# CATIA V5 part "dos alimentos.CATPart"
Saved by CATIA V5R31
Part number: dos alimentos
Bounding box of the stored display mesh (mm): x -77 to 71.25, y -71.051 to 71.051, z -5 to 175
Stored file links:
  C:\Users\189361\Desktop\piezas del comedero\piezas del comedero\dos alimentos.CATPart
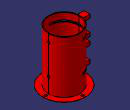
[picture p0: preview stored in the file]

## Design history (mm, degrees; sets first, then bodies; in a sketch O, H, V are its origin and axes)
Body1 (main body)
  Sketch1 on xy-plane, origin (0, 0, 0), H (1, 0, 0), V (0, 1, 0)
    construction circle A1 centre (0, 0) radius 62.25
    circle A2 centre (0, 62.25) radius 4.5
    point P1 (0, 62.25)
    circle A3 centre (62.25, 0) radius 4.5
    point P2 (62.25, 0)
    circle A4 centre (0, -62.25) radius 4.5
    circle A5 centre (-62.25, 0) radius 4.5
    circle A6 centre (0, 0) radius 71.25
    circle A7 centre (0, 0) radius 50
    circle A8 centre (0, 0) radius 52.5
    radius A1 = 62.25
    radius A2 = 4.5
    distance A3 A6 = 4.5
    radius A7 = 50
    radius A8 = 52.5
    coincidence: P1 A1, P1 V, P2 A1, P2 H
    equal size: A3 A2
    symmetry: A2 A4 H, A3 A5 V
  MultiPad1: profile Sketch1, domains (length 175 / length 5; length 0; length 0 / length 5; length 0; length 0; length 0; length 0)
  Fillet1: radius 5, on edge [face of MultiPad1 from Sketch1.A7 | face of MultiPad1]; edge [face of MultiPad1 | face of MultiPad1 from Sketch1.A6]
  Sketch2 on yz-plane, origin (0, 0, 0), H (0, 1, 0), V (0, 0, 1)
    construction line L1 (0, 0) -> (0, 50)
    construction line L2 (0, 0) -> (0, 150)
    point P2 (0, 150)
    arc A1 centre (0, 150) radius 4.25 from (4.25, 150) to (3.2404, 152.75) ccw
    point P3 (-50, 152.75)
    line L3 (-50, 152.75) -> (-3.2404, 152.75)
    line L4 (50, 152.75) -> (50, 147.25)
    line L5 (50, 147.25) -> (3.2404, 147.25)
    line L6 (-50, 147.25) -> (-50, 152.75)
    point P4 (50, 152.75)
    point P5 (50, 147.25)
    point P6 (-50, 147.25)
    axis line L7 (-80.1309, 100) -> (62.8872, 100)
    point P10 (-50, 47.25)
    point P11 (50, 47.25)
    point P12 (50, 52.75)
    point P13 (-50, 52.75)
    arc A2 centre (0, 50) radius 4.25 from (4.25, 50) to (3.2404, 47.25) cw
    line L8 (-50, 47.25) -> (-3.2404, 47.25)
    line L9 (50, 47.25) -> (50, 52.75)
    line L10 (50, 52.75) -> (3.2404, 52.75)
    line L11 (-50, 52.75) -> (-50, 47.25)
    point P14 (-3.2404, 147.25)
    line L12 (-3.2404, 147.25) -> (-50, 147.25)
    point P15 (3.2404, 147.25)
    point P16 (3.2404, 152.75)
    line L13 (3.2404, 152.75) -> (50, 152.75)
    point P17 (-3.2404, 152.75)
    point P18 (-3.2404, 52.75)
    line L14 (-3.2404, 52.75) -> (-50, 52.75)
    point P19 (3.2404, 52.75)
    point P20 (3.2404, 47.25)
    line L15 (3.2404, 47.25) -> (50, 47.25)
    point P21 (-3.2404, 47.25)
    point P22 (3.2404, 147.25)
    arc A3 centre (0, 150) radius 4.25 from (3.2404, 147.25) to (4.25, 150) ccw
    point P23 (4.25, 150)
    point P24 (4.25, 150)
    point P25 (3.2404, 152.75)
    arc A4 centre (0, 150) radius 4.25 from (3.2404, 152.75) to (-3.2404, 152.75) ccw
    point P26 (-3.2404, 152.75)
    arc A5 centre (0, 150) radius 4.25 from (-3.2404, 152.75) to (-3.2404, 147.25) ccw
    point P27 (-3.2404, 147.25)
    arc A6 centre (0, 150) radius 4.25 from (-3.2404, 147.25) to (3.2404, 147.25) ccw
    point P28 (-3.2404, 52.75)
    arc A7 centre (0, 50) radius 4.25 from (-3.2404, 52.75) to (3.2404, 52.75) cw
    point P29 (4.25, 50)
    point P30 (4.25, 50)
    point P31 (3.2404, 52.75)
    arc A8 centre (0, 50) radius 4.25 from (3.2404, 52.75) to (4.25, 50) cw
    point P32 (3.2404, 47.25)
    arc A9 centre (0, 50) radius 4.25 from (3.2404, 47.25) to (-3.2404, 47.25) cw
    point P33 (-3.2404, 47.25)
    arc A10 centre (0, 50) radius 4.25 from (-3.2404, 47.25) to (-3.2404, 52.75) cw
    length L1 = 50
    length L2 = 150
    radius A1 = 4.25
    length L4 = 5.5
    distance L4 L2 = 50
    distance P2 L3 = 2.75
    distance L7 P2 = 50
    distance P3 P4 = 100
    vertical: L1 V, L2 V, L4 V, L6 V
    horizontal: L3 H, L5 H, L7 H
    symmetry: P3 P10 L7, P4 P11 L7, P5 P12 L7, P6 P13 L7, A1 A2 L7, L3 L8 L7, L4 L9 L7, L5 L10 L7, L6 L11 L7
    coincidence: L5 L12, A1 P14, A1 P15, L3 L13, A1 P16, A1 P17, L10 L14, A2 P18, A2 P19, L8 L15, A2 P20, A2 P21, A1 A3, P23 P24, L5 P22, A1 A4, L3 P25, A4 A5, L3 P26, A5 A6, L12 P27, A2 A7, P29 P30, L14 P28, A7 A8, L10 P31, A2 A9, L15 P32, A9 A10, L8 P33, P14 P27, P15 P22, P16 P25, P17 P26, P18 P28, P19 P31, P20 P32, P21 P33
  MultiPocket1: profile Sketch2, domains (length 55 / length 55; length 55; length 55; length 55 / length 55; length 55; length 55)
  Plane1: type Offset, RefPlane yz-plane, Offset 60, reversed
  Sketch3 on Plane1, origin (-60, 0, 0), H (0, 1, 0), V (0, 0, 1)
    construction circle A1 centre (5, 164) radius 2.2
    point P1 (5, 164)
    construction line L1 (0, 150) -> (0, 166)
    point P2 (0, 150)
    point P3 (0, 166)
    reference projected arc E1 centre (0, 150) radius 4.25 from (-3.2404, 147.25) to (3.2404, 147.25) ccw from edge [face of MultiPad1 from Sketch1.A8 | face of MultiPocket1 from Sketch2.A6]
    point P4 (10, 166)
    construction line L2 (10, 166) -> (-10, 166)
    construction line L3 (-10, 166) -> (-10, 112)
    construction line L4 (-10, 112) -> (10, 112)
    construction line L5 (10, 112) -> (10, 166)
    point P5 (-10, 166)
    point P6 (-10, 112)
    point P7 (10, 112)
    construction circle A2 centre (5, 114) radius 2.2
    point P8 (5, 114)
    construction line L6 (5, 164) -> (5, 100.8929)
    reference projected line E2 through (0, 0) direction (0, 1) from axis of face of MultiPad1 from Sketch1.A8
    construction circle A3 centre (-5, 114) radius 2.2
    construction circle A4 centre (-5, 164) radius 2.2
    point P14 (10, 172)
    line L7 (10, 172) -> (-10, 172)
    line L8 (-10, 172) -> (-10, 160)
    line L9 (-10, 160) -> (10, 160)
    line L10 (10, 160) -> (10, 172)
    point P15 (-10, 172)
    point P16 (-10, 160)
    point P17 (10, 160)
    point P18 (-10, 119)
    point P19 (10, 119)
    line L11 (10, 119) -> (-10, 119)
    point P20 (10, 107)
    line L12 (10, 107) -> (10, 119)
    point P21 (-10, 107)
    line L13 (-10, 107) -> (10, 107)
    line L14 (-10, 119) -> (-10, 107)
    axis line L15 (-82.5761, 100) -> (84.9534, 100)
    construction circle A5 centre (5, 36) radius 2.2
    point P25 (0, 34)
    point P26 (0, 50)
    construction line L16 (0, 50) -> (0, 34)
    point P27 (10, 34)
    point P28 (-10, 34)
    construction line L17 (10, 34) -> (-10, 34)
    point P29 (-10, 88)
    construction line L18 (-10, 34) -> (-10, 88)
    point P30 (10, 88)
    construction line L19 (-10, 88) -> (10, 88)
    construction line L20 (10, 88) -> (10, 34)
    construction circle A6 centre (5, 86) radius 2.2
    construction circle A7 centre (-5, 86) radius 2.2
    construction circle A8 centre (-5, 36) radius 2.2
    point P34 (10, 28)
    point P35 (-10, 28)
    point P36 (-10, 40)
    point P37 (10, 40)
    point P38 (-10, 81)
    point P39 (10, 81)
    point P40 (10, 93)
    point P41 (-10, 93)
    line L21 (10, 28) -> (-10, 28)
    line L22 (-10, 28) -> (-10, 40)
    line L23 (-10, 40) -> (10, 40)
    line L24 (10, 40) -> (10, 28)
    line L25 (10, 81) -> (-10, 81)
    line L26 (10, 93) -> (10, 81)
    line L27 (-10, 93) -> (10, 93)
    line L28 (-10, 81) -> (-10, 93)
    radius A1 = 2.2
    length L1 = 16
    length L2 = 20
    length L5 = 54
    distance L3 L1 = 10
    distance L5 P1 = 5
    distance P8 P1 V = 50
    length L8 = 12
    distance L9 L2 = 6
    distance P1 P2 V = 14
    distance P8 L11 = 5
    length L12 = 12
    distance L11 L9 = 41 (reference)
    distance L15 P2 = 50
    coincidence: P2 V, P3 L2, L6 P8, L10 L5, L8 L3, L12 L5, L14 L3
    vertical: L1 V, L3 V, L5 V, L6 V, L8 V, L10 V
    concentricity: P2 E1
    horizontal: L2 H, L4 H, L7 H, L9 H, L13 H, L11 H, L15 H
    equal size: A1 A2
    symmetry: A2 A3 E2, A1 A4 E2, A1 A5 L15, P3 P25 L15, P2 P26 L15, L1 L16 L15, P4 P27 L15, P5 P28 L15, L2 L17 L15, P6 P29 L15, L3 L18 L15, P7 P30 L15, L4 L19 L15, L5 L20 L15, A2 A6 L15, A3 A7 L15, A4 A8 L15, P14 P34 L15, P15 P35 L15, P16 P36 L15, P17 P37 L15, P18 P38 L15, P19 P39 L15, P20 P40 L15, P21 P41 L15, L7 L21 L15, L8 L22 L15, L9 L23 L15, L10 L24 L15, L11 L25 L15, L12 L26 L15, L13 L27 L15, L14 L28 L15
  Pad1: profile Sketch3, direction (1, 0, 0), up to the existing solid (limit type 2), opposite side length 17
  Sketch4 on start face of Pad1, origin (-77, 0, 0), H (0, -1, 0), V (0, 0, 1)
    circle A1 centre (-5, 163.5667) radius 2.2
    point P1 (-5, 163.5667)
    construction line L1 (0, 149.5667) -> (0, 165.5667)
    point P2 (0, 149.5667)
    point P3 (0, 165.5667)
    construction line L2 (-10, 165.5667) -> (10, 165.5667)
    construction line L3 (10, 165.5667) -> (10, 111.5667)
    construction line L4 (10, 111.5667) -> (-10, 111.5667)
    construction line L5 (-10, 111.5667) -> (-10, 165.5667)
    construction line L6 (-66.4446, 138.5667) -> (8.8092, 138.5667)
    circle A2 centre (-5, 113.5667) radius 2.2
    reference projected line E1 through (0, 0) direction (0, 1) from axis of face of MultiPad1 from Sketch1.A8
    circle A3 centre (5, 163.5667) radius 2.2
    circle A4 centre (5, 113.5667) radius 2.2
    axis line L7 (-62.1059, 99.5667) -> (-32.3335, 99.5667)
    circle A5 centre (-5, 85.5667) radius 2.2
    circle A6 centre (5, 85.5667) radius 2.2
    circle A7 centre (5, 35.5667) radius 2.2
    circle A8 centre (-5, 35.5667) radius 2.2
    radius A1 = 2.2
    length L1 = 16
    length L2 = 20
    length L5 = 54
    distance L3 L1 = 10
    distance P1 L2 = 2
    distance P1 L5 = 5
    distance L6 L2 = 27
    distance P2 L7 = 50
    coincidence: P2 V, P3 L2
    vertical: L1 V, L3 V, L5 V
    horizontal: L2 H, L4 H, L6 H, L7 H
    symmetry: A1 A2 L6, A1 A3 E1, A2 A4 E1, A2 A5 L7, A4 A6 L7, A3 A7 L7, A1 A8 L7
  Pocket1: profile Sketch4, direction (1, 0, 0), length 7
